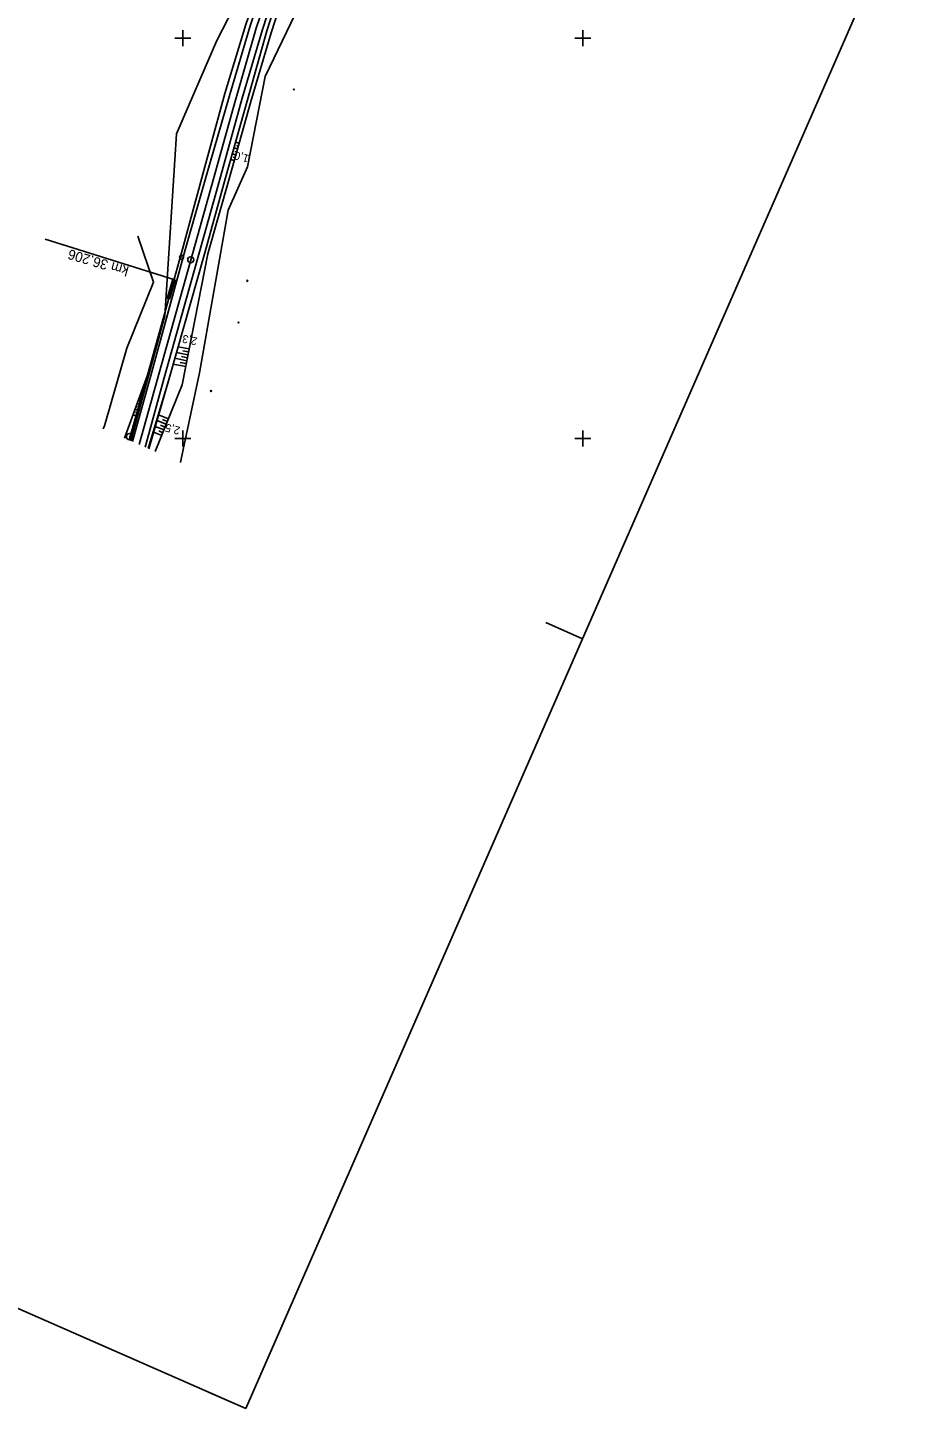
# Model space of a CAD drawing. Extents: x -806856 to -806332, y -1151642 to -1150946.
# Drawn here: x -806638.8 to -806415.8, y -1151642.4 to -1151297.3 of the extents above; entities that cross this region are included whole.
import ezdxf

# ---------------------------------------------------------------- set-up
doc = ezdxf.new("R2010")
doc.units = 0
for name, color, linetype in [('0381KM032-037P - Vrstva 1', 7, 'Continuous'), ('0381KM032-037P - Vrstva 17', 7, 'Continuous'), ('0381KM032-037P - Vrstva 4', 7, 'Continuous'), ('0381KM032-037P - Vrstva 48', 7, 'Continuous'), ('0381KM032-037P - Vrstva 49', 7, 'Continuous'), ('0381KM032-037P - Vrstva 7', 7, 'Continuous'), ('0381KM032-037P - Vrstva 9', 7, 'Continuous'), ('formát', 7, 'Continuous'), ('hran DP - hran DP', 7, 'Continuous'), ('krizky_1000 - Vrstva 1', 7, 'Continuous'), ('vyt_sit - stávající', 7, 'Continuous')]:
    doc.layers.add(name, color=color, linetype=linetype)

msp = doc.modelspace()

# ---------------------------------------------------------------- linework, layer by layer
at = {"layer": '0381KM032-037P - Vrstva 1'}
for points in [[(-806575.26, -1151278.66), (-806581.61, -1151297.45), (-806587.32, -1151317.2)], [(-806587.32, -1151317.2), (-806595.77, -1151347.36), (-806604.1, -1151377.15), (-806610.94, -1151401.52)]]:
    msp.add_lwpolyline(points, dxfattribs=at)
at = {"layer": '0381KM032-037P - Vrstva 17'}
msp.add_lwpolyline([(-806611.24, -1151349.41), (-806607.31, -1151360.99), (-806614.01, -1151377.45), (-806619.53, -1151396.86), (-806619.89, -1151397.6)], dxfattribs=at)
at = {"layer": '0381KM032-037P - Vrstva 4'}
for points in [[(-806534.73, -1151198.81), (-806545.37, -1151216.39), (-806553.18, -1151229.13), (-806561.58, -1151243.53), (-806567.96, -1151255.6), (-806574.3, -1151269.24), (-806578.76, -1151280.27), (-806579.4, -1151282.54), (-806584.22, -1151296.56), (-806589.48, -1151313.82), (-806594.95, -1151333.92), (-806600.1, -1151352.67), (-806608.81, -1151384.22), (-806613.08, -1151400.58)], [(-806534.14, -1151199.19), (-806544.55, -1151216.75), (-806552.31, -1151229.7), (-806560.71, -1151244.03), (-806567.24, -1151256.24), (-806573.52, -1151269.73), (-806577.97, -1151280.92), (-806578.5, -1151282.67), (-806583.15, -1151296.86), (-806588.26, -1151314.07), (-806594.08, -1151334.22), (-806599.38, -1151352.89), (-806608.02, -1151384.26), (-806612.6, -1151400.79)], [(-806531.11, -1151200.55), (-806541.48, -1151217.8), (-806549.08, -1151230.92), (-806557.69, -1151245.47), (-806564.05, -1151257.36), (-806570.21, -1151270.63), (-806574.62, -1151281.75), (-806575.45, -1151283.67), (-806580.1, -1151297.77), (-806585.12, -1151314.97), (-806590.56, -1151334.63), (-806595.8, -1151353.37), (-806604.61, -1151384.9), (-806609.41, -1151402.19)], [(-806530.22, -1151201.05), (-806540.66, -1151218.65), (-806548.31, -1151231.35), (-806556.78, -1151246.08), (-806563.07, -1151257.89), (-806569.22, -1151271.02), (-806574.1, -1151282.08), (-806574.48, -1151284.1), (-806578.97, -1151298.16), (-806583.83, -1151315.38), (-806589.34, -1151334.88), (-806594.45, -1151353.63), (-806603.42, -1151385.04), (-806608.69, -1151402.5)]]:
    msp.add_lwpolyline(points, dxfattribs=at)
at = {"layer": '0381KM032-037P - Vrstva 48'}
for p, q in [((-806585.91, -1151326.21), (-806586.82, -1151325.96)), ((-806586.11, -1151326.94), (-806586.57, -1151326.81)), ((-806587.11, -1151330.55), (-806588.04, -1151330.29)), ((-806586.71, -1151329.1), (-806587.63, -1151328.85)), ((-806586.91, -1151329.82), (-806587.38, -1151329.7)), ((-806586.31, -1151327.66), (-806587.23, -1151327.4)), ((-806586.51, -1151328.38), (-806586.97, -1151328.25)), ((-806598.69, -1151379.1), (-806601.56, -1151378.53)), ((-806598.39, -1151377.63), (-806601.15, -1151377.08)), ((-806598.54, -1151378.36), (-806599.95, -1151378.08)), ((-806599.27, -1151382.04), (-806602.39, -1151381.42)), ((-806598.98, -1151380.57), (-806601.97, -1151379.98)), ((-806599.12, -1151381.31), (-806600.65, -1151381)), ((-806598.83, -1151379.83), (-806600.3, -1151379.54)), ((-806611.67, -1151391.97), (-806611.36, -1151392.08)), ((-806611.41, -1151391.27), (-806610.85, -1151391.47)), ((-806611.15, -1151390.56), (-806610.9, -1151390.65)), ((-806610.89, -1151389.86), (-806610.44, -1151390.02)), ((-806612.45, -1151394.08), (-806611.67, -1151394.37)), ((-806612.19, -1151393.38), (-806611.83, -1151393.51)), ((-806611.93, -1151392.67), (-806611.26, -1151392.92)), ((-806604.12, -1151396.48), (-806606.45, -1151395.55)), ((-806603.57, -1151395.08), (-806606.03, -1151394.1)), ((-806603.85, -1151395.78), (-806605.04, -1151395.3)), ((-806605.24, -1151399.26), (-806607.28, -1151398.45)), ((-806604.68, -1151397.87), (-806606.87, -1151397)), ((-806604.96, -1151398.57), (-806606.02, -1151398.14)), ((-806604.4, -1151397.17), (-806605.53, -1151396.72))]:
    msp.add_line(p, q, dxfattribs=at)
at = {"layer": '0381KM032-037P - Vrstva 49'}
for p, q in [((-806572.06, -1151312.59), (-806572.42, -1151312.95)), ((-806572.42, -1151312.59), (-806572.06, -1151312.95)), ((-806583.68, -1151360.44), (-806584.03, -1151360.8)), ((-806584.03, -1151360.44), (-806583.68, -1151360.8)), ((-806585.91, -1151370.83), (-806586.27, -1151371.18)), ((-806586.27, -1151370.83), (-806585.91, -1151371.18)), ((-806608.81, -1151384.22), (-806613.38, -1151400.45)), ((-806608.81, -1151384.22), (-806613.08, -1151400.58)), ((-806592.76, -1151387.98), (-806593.11, -1151388.33)), ((-806593.11, -1151387.98), (-806592.75, -1151388.33))]:
    msp.add_line(p, q, dxfattribs=at)
for points in [[(-806520.01, -1151188.39), (-806536.66, -1151214.61), (-806549.93, -1151238.4), (-806571.09, -1151278.57), (-806574.7, -1151288.79), (-806577.92, -1151298.67), (-806582.99, -1151315.77), (-806588.39, -1151335.12), (-806593.7, -1151353.88), (-806600.16, -1151386.57)], [(-806535.85, -1151198.12), (-806546.61, -1151215.57), (-806553.18, -1151229.13), (-806561.58, -1151243.53), (-806567.96, -1151255.6), (-806574.3, -1151269.24), (-806578.76, -1151280.27), (-806579.4, -1151282.54), (-806584.22, -1151296.56), (-806589.48, -1151313.82), (-806594.95, -1151333.92), (-806600.1, -1151352.67), (-806608.81, -1151384.22), (-806614.6, -1151399.91)], [(-806574.1, -1151282.08), (-806574.48, -1151284.1), (-806578.97, -1151298.16), (-806583.83, -1151315.38), (-806589.34, -1151334.88), (-806594.45, -1151353.63), (-806603.42, -1151385.04), (-806608.48, -1151402.59)], [(-806608.69, -1151402.5), (-806603.42, -1151385.04)], [(-806600.16, -1151386.57), (-806606.86, -1151403.3)]]:
    msp.add_lwpolyline(points, dxfattribs=at)
at = {"layer": '0381KM032-037P - Vrstva 7'}
msp.add_line((-806600.34, -1151354.71), (-806600.24, -1151354.71), dxfattribs=at)
for centre, radius in [((-806600.29, -1151354.71), 0.5), ((-806598, -1151355.35), 0.75)]:
    msp.add_circle(centre, radius, dxfattribs=at)
at = {"layer": '0381KM032-037P - Vrstva 9'}
for p, q in [((-806602.2, -1151360.29), (-806634.39, -1151350.17)), ((-806602.49, -1151360.21), (-806603.91, -1151365)), ((-806603.33, -1151365.17), (-806601.91, -1151360.38)), ((-806602.49, -1151360.21), (-806603.06, -1151360.04)), ((-806601.91, -1151360.38), (-806602.49, -1151360.21)), ((-806603.91, -1151365), (-806603.33, -1151365.17))]:
    msp.add_line(p, q, dxfattribs=at)
at = {"layer": 'formát'}
for p, q in [((-806415.83, -1151257.68), (-806500.03, -1151450.06)), ((-806509.19, -1151446.05), (-806500.03, -1151450.06)), ((-806509.19, -1151446.05), (-806500.03, -1151450.06)), ((-806500.03, -1151450.06), (-806584.22, -1151642.44)), ((-806856.31, -1151523.36), (-806584.22, -1151642.44)), ((-806593.38, -1151638.43), (-806584.22, -1151642.44))]:
    msp.add_line(p, q, dxfattribs=at)
at = {"layer": 'hran DP - hran DP'}
for p, q in [((-806591.51, -1151300.57), (-806576.79, -1151271.69)), ((-806561.98, -1151273.31), (-806579.39, -1151309.52)), ((-806601.55, -1151323.84), (-806591.51, -1151300.57)), ((-806579.39, -1151309.52), (-806583.8, -1151332.16)), ((-806604.52, -1151369.36), (-806601.55, -1151323.84)), ((-806583.8, -1151332.16), (-806588.67, -1151342.95)), ((-806588.67, -1151342.95), (-806595.8, -1151383.59)), ((-806612.97, -1151400.63), (-806604.52, -1151369.36)), ((-806595.8, -1151383.59), (-806599.86, -1151402.77)), ((-806599.86, -1151402.77), (-806600.56, -1151406.06))]:
    msp.add_line(p, q, dxfattribs=at)
at = {"layer": 'krizky_1000 - Vrstva 1'}
for points in [[(-806600, -1151298), (-806600, -1151302)], [(-806500, -1151298), (-806500, -1151302)], [(-806602, -1151300), (-806598, -1151300)], [(-806502, -1151300), (-806498, -1151300)], [(-806600, -1151398), (-806600, -1151402)], [(-806500, -1151398), (-806500, -1151402)], [(-806602, -1151400), (-806598, -1151400)], [(-806502, -1151400), (-806498, -1151400)]]:
    msp.add_lwpolyline(points, dxfattribs=at)
at = {"layer": 'vyt_sit - stávající'}
msp.add_line((-806613.39, -1151399.56), (-806613.29, -1151399.56), dxfattribs=at)
msp.add_circle((-806613.33, -1151399.56), 0.756, dxfattribs=at)

# ---------------------------------------------------------------- texts
at = {"layer": '0381KM032-037P - Vrstva 48'}
for s, rotation, p in [('1,0', 164.2247, (-806583.24, -1151329.23)), ('2,3', 167.817, (-806596.23, -1151374.85)), ('2,5', 166.3296, (-806600.51, -1151397.17))]:
    msp.add_text(s, height=2, rotation=rotation, dxfattribs=at).set_placement(p)
at = {"layer": '0381KM032-037P - Vrstva 9'}
msp.add_text('km 36,206', height=2.5, rotation=163.5076, dxfattribs=at).set_placement((-806613.29, -1151357.1))

doc.saveas('drawing.dxf')
